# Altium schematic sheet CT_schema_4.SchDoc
size 212 x 173 mm
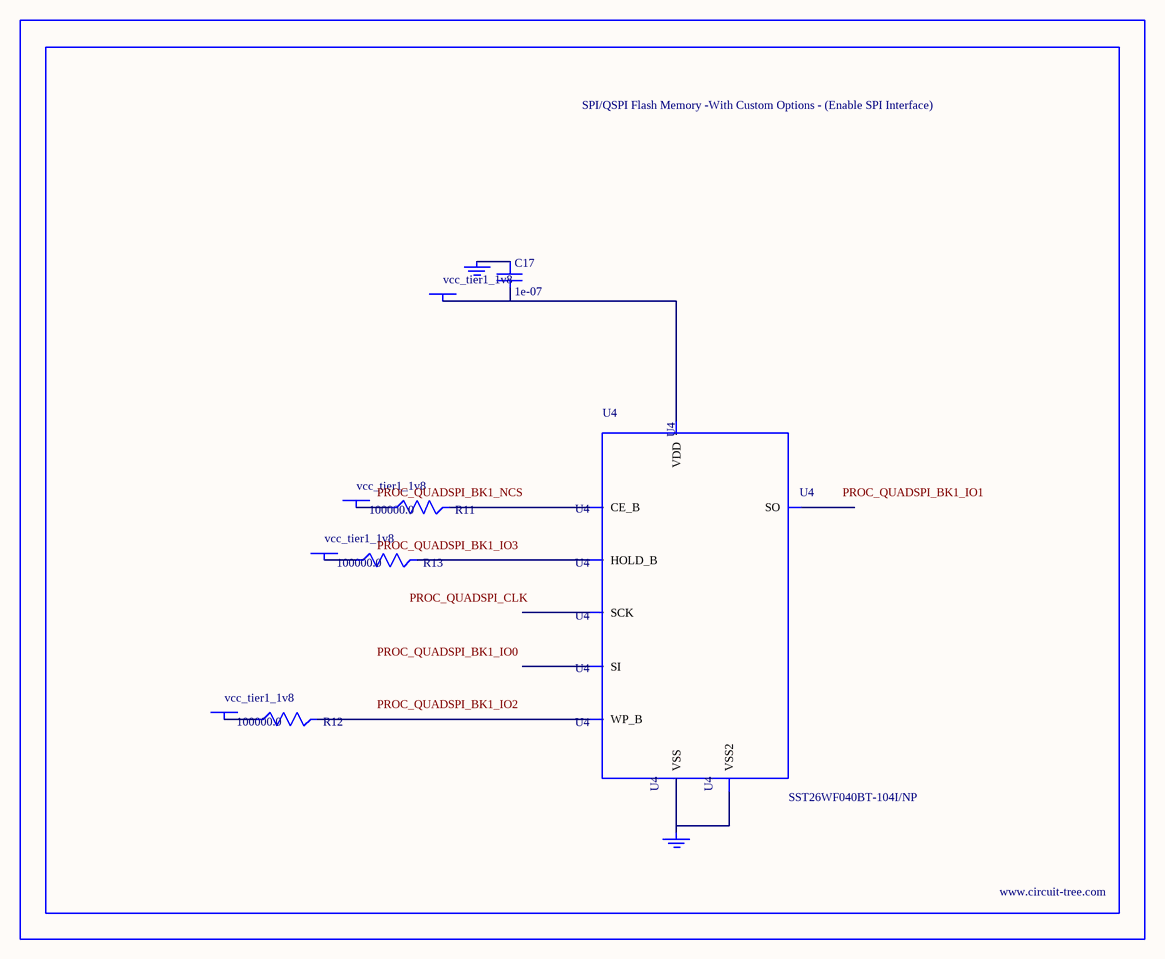
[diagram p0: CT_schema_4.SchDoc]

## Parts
BORDER3  (no value)
C17  1e-07  [C0402]
GND_INSTANCE_3_0  (no value)
GND_INSTANCE_3_1  (no value)
POWER_INSTANCE_3_0  vcc_tier1_1v8
POWER_INSTANCE_3_1  vcc_tier1_1v8
POWER_INSTANCE_3_2  vcc_tier1_1v8
POWER_INSTANCE_3_3  vcc_tier1_1v8
R11  100000.0  [R0603]
R12  100000.0  [R0603]
R13  100000.0  [R0603]
U4  SST26WF040BT-104I/NP  [USON-8]

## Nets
NetC17_1: C17.1 GND_INSTANCE_3_0.0(GND)
NetC17_2: C17.2 POWER_INSTANCE_3_3.0(PWR) U4.8(VDD)
NetGND_INSTANCE_3_1_0: GND_INSTANCE_3_1.0(GND) U4.4(VSS) U4.9(VSS2)
NetPOWER_INSTANCE_3_0_0: POWER_INSTANCE_3_0.0(PWR) R11.1
NetPOWER_INSTANCE_3_1_0: POWER_INSTANCE_3_1.0(PWR) R12.1
NetPOWER_INSTANCE_3_2_0: POWER_INSTANCE_3_2.0(PWR) R13.1
NetR11_2: R11.2 U4.1(CE_B)
NetR12_2: R12.2 U4.3(WP_B)
NetR13_2: R13.2 U4.7(HOLD_B)

Not connected (* = marked no-connect by the designer): U4 2(SO) 5(SI) 6(SCK)

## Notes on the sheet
- Labels drawn without touching a wire or pin: PROC_QUADSPI_BK1_IO0, PROC_QUADSPI_BK1_IO1, PROC_QUADSPI_BK1_IO2, PROC_QUADSPI_BK1_IO3, PROC_QUADSPI_BK1_NCS, PROC_QUADSPI_CLK

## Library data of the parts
BORDER3 = BORDER_PAGE3
C17 = C0402C104K3RACTU
GND_INSTANCE_3_0 GND_INSTANCE_3_1 = GND
POWER_INSTANCE_3_0-POWER_INSTANCE_3_3 = PWR
R11-R13 = RC0603JR-07100KL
